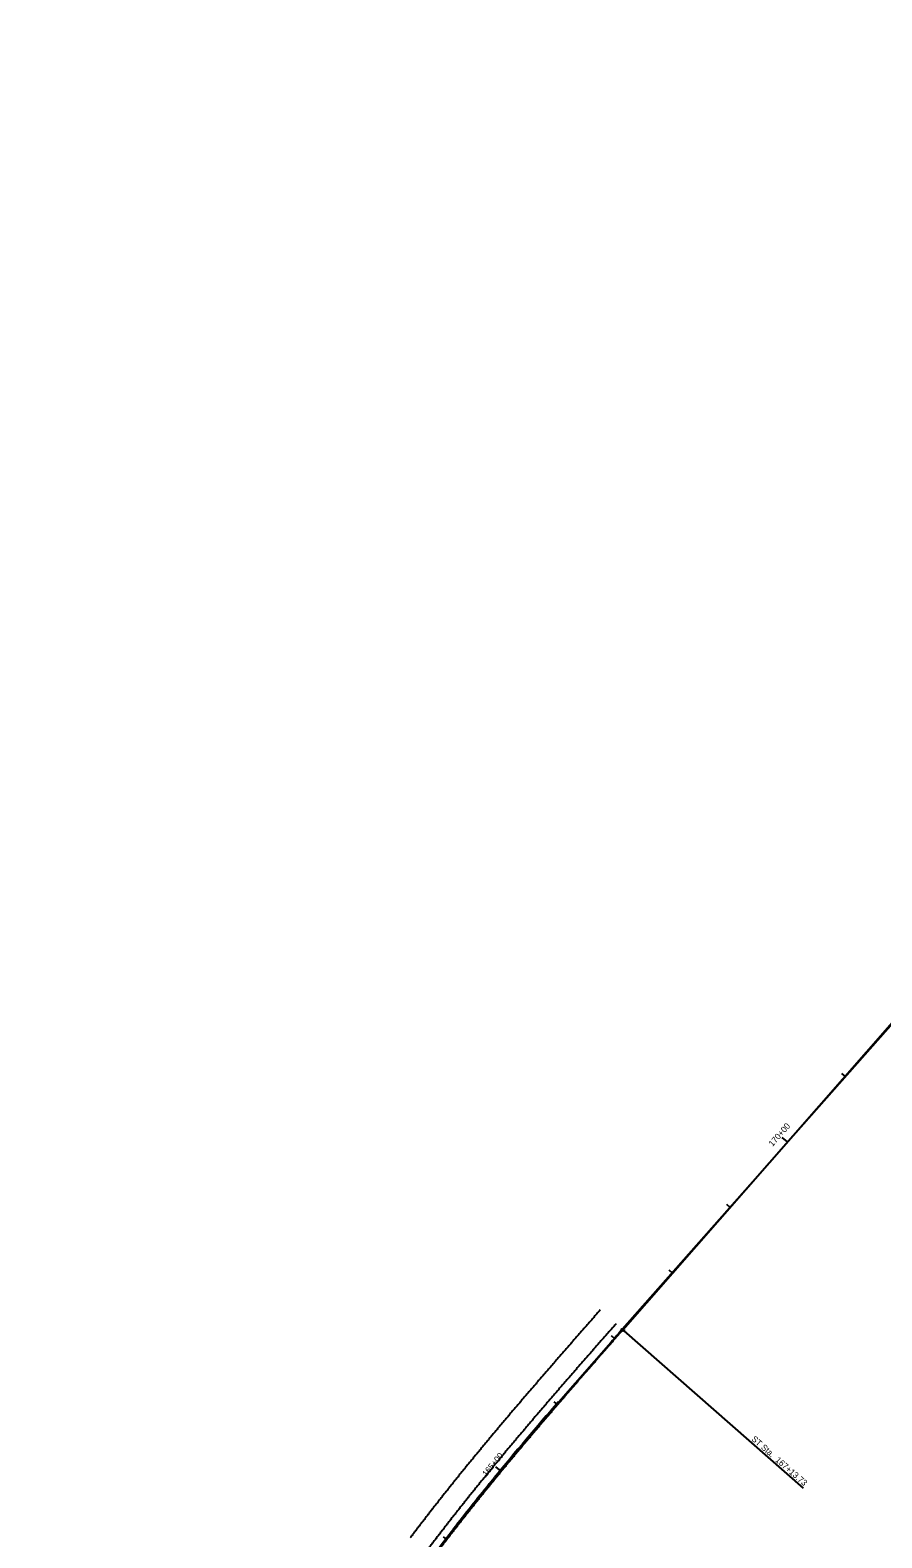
# Model space of a CAD drawing. Extents: x 1722038 to 1726172, y 967033 to 975427.
# Drawn here: x 1723921 to 1724897, y 973700 to 975427 of the extents above; entities that cross this region are included whole.
import ezdxf

# ---------------------------------------------------------------- set-up
doc = ezdxf.new("R2010")
doc.units = 0
for name, color, linetype in [('Prop Horizontal Alignment', 7, 'Continuous'), ('Prop Horizontal Alignment Station Label', 7, 'Continuous'), ('Prop Horizontal Alignment Tick Label', 7, 'Continuous'), ('Prop Horizontal Alignment Tick Large', 7, 'Continuous'), ('Prop Horizontal Alignment Tick Small', 7, 'Continuous')]:
    doc.layers.add(name, color=color, linetype=linetype)

msp = doc.modelspace()

# ---------------------------------------------------------------- linework, layer by layer
at = {"layer": 'Prop Horizontal Alignment'}
for p, q in [((1724599.7, 973939.6), (1725915.1, 975427.3)), ((1724600, 973938.6), (1725686.5, 975177.7)), ((1724526.4, 973856.2), (1724586.5, 973924.6)), ((1724446.9, 973762.1), (1724452.5, 973769))]:
    msp.add_line(p, q, dxfattribs=at)
for centre, radius, start, end in [((1731342.4, 967978.3), 9000, 138.51969, 138.64702), ((1726778.3, 971874.1), 3000, 138.647, 140.8311), ((1726540.1, 972056.7), 2700, 140.8311, 142.226), ((1726238.9, 972290.2), 2318.8, 142.226, 178.7913)]:
    msp.add_arc(centre, radius, start, end, dxfattribs=at)
for points in [[(1724574, 973961.4), (1724571, 973958), (1724568, 973954.5), (1724565, 973951.1), (1724562, 973947.7), (1724559, 973944.2), (1724556, 973940.8), (1724553, 973937.4), (1724549.9, 973933.9), (1724546.9, 973930.5), (1724543.9, 973927), (1724540.9, 973923.6), (1724537.9, 973920.2), (1724534.9, 973916.7), (1724531.9, 973913.3), (1724528.9, 973909.8), (1724525.9, 973906.4), (1724522.9, 973902.9), (1724519.9, 973899.5), (1724516.9, 973896), (1724513.9, 973892.6), (1724510.9, 973889.1), (1724507.9, 973885.6), (1724504.9, 973882.2), (1724501.9, 973878.7), (1724498.9, 973875.2), (1724495.9, 973871.8), (1724492.9, 973868.3), (1724489.9, 973864.8), (1724486.9, 973861.3), (1724483.9, 973857.8), (1724481, 973854.3), (1724478, 973850.9), (1724475, 973847.4), (1724472, 973843.9), (1724469.1, 973840.4), (1724466.1, 973836.9), (1724463.1, 973833.3), (1724460.2, 973829.8), (1724457.2, 973826.3), (1724454.2, 973822.8), (1724451.3, 973819.3), (1724448.3, 973815.7), (1724445.4, 973812.2), (1724442.4, 973808.7), (1724439.5, 973805.1), (1724436.6, 973801.6), (1724433.6, 973798), (1724430.7, 973794.5), (1724427.8, 973790.9), (1724424.9, 973787.4), (1724421.9, 973783.8), (1724419, 973780.2), (1724416.1, 973776.7), (1724413.2, 973773.1), (1724410.3, 973769.5), (1724407.4, 973765.9), (1724404.5, 973762.3), (1724401.6, 973758.7), (1724398.8, 973755.1), (1724395.9, 973751.5), (1724393, 973747.9), (1724390.2, 973744.3), (1724387.3, 973740.6), (1724384.4, 973737), (1724381.6, 973733.4), (1724378.8, 973729.7), (1724375.9, 973726.1), (1724373.1, 973722.4), (1724370.3, 973718.7), (1724367.4, 973715.1), (1724364.6, 973711.4), (1724361.8, 973707.7), (1724359, 973704), (1724356.3, 973700.4)], [(1724592.1, 973945.6), (1724589.1, 973942.1), (1724586, 973938.7), (1724583, 973935.3), (1724580, 973931.8), (1724577, 973928.4), (1724574, 973925), (1724571, 973921.5), (1724568, 973918.1), (1724565, 973914.7), (1724562, 973911.2), (1724559, 973907.8), (1724556, 973904.4), (1724553, 973900.9), (1724550, 973897.5), (1724547, 973894.1), (1724544, 973890.6), (1724541, 973887.2), (1724538, 973883.7), (1724535, 973880.3), (1724532, 973876.8), (1724529, 973873.4), (1724526, 973869.9), (1724523, 973866.5), (1724520.1, 973863), (1724517.1, 973859.6), (1724514.1, 973856.1), (1724511.1, 973852.6), (1724508.1, 973849.2), (1724505.2, 973845.7), (1724502.2, 973842.2), (1724499.2, 973838.8), (1724496.2, 973835.3), (1724493.3, 973831.8), (1724490.3, 973828.3), (1724487.4, 973824.8), (1724484.4, 973821.3), (1724481.5, 973817.9), (1724478.5, 973814.4), (1724475.6, 973810.9), (1724472.6, 973807.4), (1724469.7, 973803.9), (1724466.7, 973800.4), (1724463.8, 973796.8), (1724460.9, 973793.3), (1724458, 973789.8), (1724455.1, 973786.3), (1724452.1, 973782.8), (1724449.2, 973779.2), (1724446.3, 973775.7), (1724443.4, 973772.2), (1724440.5, 973768.6), (1724437.6, 973765.1), (1724434.7, 973761.5), (1724431.9, 973758), (1724429, 973754.4), (1724426.1, 973750.9), (1724423.2, 973747.3), (1724420.4, 973743.7), (1724417.5, 973740.1), (1724414.7, 973736.6), (1724411.8, 973733), (1724409, 973729.4), (1724406.2, 973725.8), (1724403.3, 973722.2), (1724400.5, 973718.6), (1724397.7, 973715), (1724394.9, 973711.4), (1724392.1, 973707.7), (1724389.3, 973704.1), (1724386.5, 973700.5), (1724383.7, 973696.8), (1724380.9, 973693.2), (1724378.2, 973689.5), (1724375.4, 973685.9)], [(1724600, 973938.6), (1724596.9, 973935.2), (1724593.9, 973931.8), (1724590.9, 973928.3), (1724587.9, 973924.9), (1724584.9, 973921.5), (1724581.9, 973918.1), (1724578.9, 973914.6), (1724575.9, 973911.2), (1724572.9, 973907.8), (1724569.9, 973904.3), (1724566.9, 973900.9), (1724563.9, 973897.5), (1724560.9, 973894), (1724557.9, 973890.6), (1724554.9, 973887.2), (1724551.9, 973883.7), (1724548.9, 973880.3), (1724545.9, 973876.8), (1724542.9, 973873.4), (1724539.9, 973869.9), (1724537, 973866.5), (1724534, 973863.1), (1724531, 973859.6), (1724528, 973856.2), (1724525, 973852.7), (1724522, 973849.2), (1724519.1, 973845.8), (1724516.1, 973842.3), (1724513.1, 973838.9), (1724510.2, 973835.4), (1724507.2, 973831.9), (1724504.2, 973828.5), (1724501.3, 973825), (1724498.3, 973821.5), (1724495.4, 973818), (1724492.4, 973814.6), (1724489.5, 973811.1), (1724486.5, 973807.6), (1724483.6, 973804.1), (1724480.7, 973800.6), (1724477.7, 973797.1), (1724474.8, 973793.6), (1724471.9, 973790.1), (1724469, 973786.6), (1724466, 973783.1), (1724463.1, 973779.6), (1724460.2, 973776.1), (1724457.3, 973772.6), (1724454.4, 973769), (1724451.5, 973765.5), (1724448.7, 973762), (1724445.8, 973758.5), (1724442.9, 973754.9), (1724440, 973751.4), (1724437.2, 973747.8), (1724434.3, 973744.3), (1724431.4, 973740.7), (1724428.6, 973737.2), (1724425.7, 973733.6), (1724422.9, 973730), (1724420.1, 973726.5), (1724417.2, 973722.9), (1724414.4, 973719.3), (1724411.6, 973715.7), (1724408.8, 973712.1), (1724406, 973708.5), (1724403.2, 973704.9), (1724400.4, 973701.3), (1724397.6, 973697.7), (1724394.8, 973694.1), (1724392.1, 973690.5), (1724389.3, 973686.8), (1724386.5, 973683.2), (1724383.8, 973679.6)]]:
    msp.add_spline(points, degree=3, dxfattribs=at)
at = {"layer": 'Prop Horizontal Alignment Station Label'}
msp.add_line((1724601.1, 973937.6), (1724806.7, 973757.3), dxfattribs=at)
msp.add_circle((1724600, 973938.6), 1.5, dxfattribs=at)
at = {"layer": 'Prop Horizontal Alignment Tick Large'}
for p, q in [((1724788.7, 974153.9), (1724782.7, 974159.1)), ((1724460.6, 973776.6), (1724454.5, 973781.7))]:
    msp.add_line(p, q, dxfattribs=at)
at = {"layer": 'Prop Horizontal Alignment Tick Small'}
for p, q in [((1724854.6, 974229.1), (1724850.9, 974232.4)), ((1724722.8, 974078.7), (1724719, 974082)), ((1724656.8, 974003.5), (1724653.1, 974006.8)), ((1724590.9, 973928.3), (1724587.1, 973931.6)), ((1724525.2, 973852.9), (1724521.4, 973856.2)), ((1724398.2, 973698.5), (1724394.2, 973701.5))]:
    msp.add_line(p, q, dxfattribs=at)

# ---------------------------------------------------------------- texts
at = {"layer": 'Prop Horizontal Alignment Station Label'}
msp.add_text('ST Sta.  167+13.73', height=7, rotation=318.7521, dxfattribs=at).set_placement((1724746.7, 973812.6))
at = {"layer": 'Prop Horizontal Alignment Tick Label'}
for s, rotation, p in [('170+00', 48.7521, (1724771.6, 974148)), ('165+00', 50.4439, (1724443.5, 973770))]:
    msp.add_text(s, height=7, rotation=rotation, dxfattribs=at).set_placement(p)

doc.saveas('drawing.dxf')
